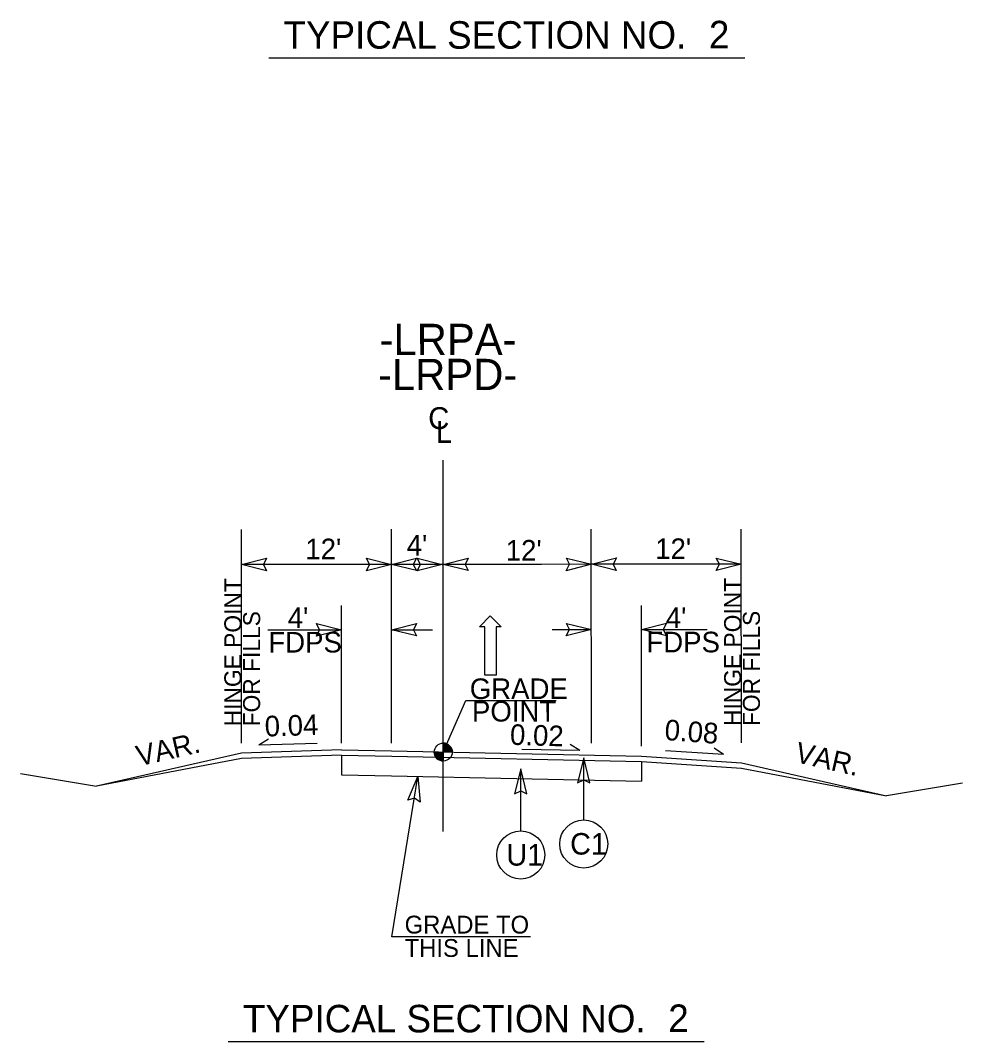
# Model space of a CAD drawing. Extents: x 2241081 to 2251104, y 658534 to 663427.
# Drawn here: x 2243910.9 to 2244287.9, y 660883.3 to 661291.9 of the extents above; entities that cross this region are included whole.
import ezdxf

# ---------------------------------------------------------------- set-up
doc = ezdxf.new("R2010")
doc.units = 0
for name, color, linetype in [('Old_Level_1', 7, 'Continuous'), ('Old_Level_11', 7, 'Continuous'), ('Old_Level_2', 7, 'Continuous'), ('Old_Level_3', 7, 'Continuous'), ('Prop Dimension Text', 7, 'Continuous'), ('Prop Lane Arrow CELL', 7, 'Continuous'), ('Prop PHM Text', 7, 'Continuous'), ('Typical Arrow Superelevation CELL', 7, 'Continuous'), ('Typical Berm Information CELL', 7, 'Continuous'), ('Typical Grade Point Symbol CELL', 7, 'Continuous'), ('Typical ID Circle CELL', 7, 'Continuous'), ('Typical Terminator CELL', 7, 'Continuous'), ('Typical Text Centerline CELL', 7, 'Continuous'), ('Typical Text Grade Point CELL', 7, 'Continuous'), ('Typical Text ID Circle CELL', 7, 'Continuous'), ('Typical Text Label CELL', 7, 'Continuous')]:
    doc.layers.add(name, color=color, linetype=linetype)

# ---------------------------------------------------------------- blocks, each defined once
blk = doc.blocks.new('TERMINATOR')
at = {"layer": 'Typical Terminator CELL'}
blk.add_lwpolyline([(-0.469, 0.081), (0, 0), (-0.471, -0.083), (-0.411, 0)], close=True, dxfattribs=at)

msp = doc.modelspace()

# ---------------------------------------------------------------- linework, layer by layer
at = {"layer": 'Old_Level_1'}
for p, q in [((2243999.39, 660998.69), (2243941.38, 660985.41)), ((2244199.38, 660994.85), (2244257.39, 660981.57))]:
    msp.add_line(p, q, dxfattribs=at)
at = {"layer": 'Old_Level_11'}
msp.add_line((2244059.46, 660925.15), (2244069.94, 660989.33), dxfattribs=at)
at = {"layer": 'Old_Level_2'}
for p, q in [((2244039.39, 660999.99), (2243999.39, 660998.69)), ((2244039.39, 660997.88), (2243999.39, 660996.58)), ((2244039.39, 660999.99), (2244059.39, 660999.56)), ((2244039.39, 660997.88), (2244039.39, 660989.99)), ((2244039.39, 660997.88), (2244059.49, 660997.45)), ((2244059.39, 660999.56), (2244159.39, 660997.42)), ((2244059.49, 660997.45), (2244159.39, 660995.31)), ((2244159.39, 660997.42), (2244199.38, 660994.85)), ((2243999.39, 660996.58), (2243941.38, 660985.41)), ((2244159.39, 660995.31), (2244159.39, 660987.42)), ((2244159.39, 660995.31), (2244199.38, 660992.73)), ((2244199.38, 660992.73), (2244257.39, 660981.57)), ((2243910.88, 660990.5), (2243941.38, 660985.41)), ((2244039.39, 660989.99), (2244059.38, 660989.56)), ((2244059.38, 660989.56), (2244159.39, 660987.42)), ((2244287.89, 660986.65), (2244257.39, 660981.57))]:
    msp.add_line(p, q, dxfattribs=at)
at = {"layer": 'Prop Dimension Text'}
for p, q in [((2243999.38, 661002.64), (2243999.33, 661088.23)), ((2244059.38, 661002.68), (2244059.33, 661088.27)), ((2244139.38, 661002.73), (2244139.33, 661088.32)), ((2244199.38, 661002.76), (2244199.33, 661088.35)), ((2244199.34, 661074.28), (2244139.34, 661074.25)), ((2244059.34, 661074.2), (2243999.34, 661074.16)), ((2244080.03, 661074.21), (2244059.34, 661074.2)), ((2244119.34, 661074.24), (2244080.03, 661074.21)), ((2244139.34, 661074.25), (2244119.34, 661074.24)), ((2244039.38, 661002.67), (2244039.35, 661057.75)), ((2244159.39, 661001.43), (2244159.35, 661057.82)), ((2244009.91, 661048.04), (2244039.36, 661048.06)), ((2244059.36, 661048.07), (2244075.73, 661048.08)), ((2244123.62, 661048.11), (2244139.36, 661048.12)), ((2244159.36, 661048.13), (2244185.69, 661048.15)), ((2244114.95, 660925.18), (2244059.46, 660925.15))]:
    msp.add_line(p, q, dxfattribs=at)
at = {"layer": 'Prop Lane Arrow CELL'}
for p, q in [((2244094.62, 661049.23), (2244098.89, 661053.57)), ((2244098.89, 661053.57), (2244103.31, 661049.23)), ((2244096.69, 661049.23), (2244094.62, 661049.23)), ((2244096.7, 661029.93), (2244096.69, 661049.23)), ((2244103.31, 661049.23), (2244101.24, 661049.23)), ((2244101.24, 661049.23), (2244101.25, 661029.94)), ((2244101.25, 661029.94), (2244096.7, 661029.93))]:
    msp.add_line(p, q, dxfattribs=at)
at = {"layer": 'Typical Arrow Superelevation CELL'}
for p, q in [((2244006.29, 661002.03), (2244010.18, 661004.43)), ((2244006.29, 661002.03), (2244029.59, 661002.73)), ((2244134.79, 660999.72), (2244130.87, 661002.08)), ((2244192.25, 660998.21), (2244188.44, 661000.74)), ((2244134.79, 660999.72), (2244111.49, 661000.18)), ((2244192.25, 660998.21), (2244168.99, 660999.67))]:
    msp.add_line(p, q, dxfattribs=at)
at = {"layer": 'Typical Grade Point Symbol CELL'}
for p, q in [((2244080.08, 661002.7), (2244080.07, 660999.12)), ((2244080.07, 660999.12), (2244080.08, 661002.7)), ((2244076.49, 660999.12), (2244080.07, 660999.12)), ((2244080.07, 660999.12), (2244080.07, 660995.54)), ((2244083.65, 660999.12), (2244080.07, 660999.12))]:
    msp.add_line(p, q, dxfattribs=at)
for points in [[(2244080.13, 660999.12), (2244080.13, 661002.7), (2244080.13, 661002.7)], [(2244080.2, 660999.12), (2244080.2, 661002.7)], [(2244080.27, 660999.12), (2244080.27, 661002.69)], [(2244080.34, 660999.12), (2244080.34, 661002.69)], [(2244080.42, 660999.12), (2244080.42, 661002.68)], [(2244080.49, 660999.12), (2244080.49, 661002.67)], [(2244080.56, 660999.12), (2244080.56, 661002.67)], [(2244080.63, 660999.12), (2244080.63, 661002.65)], [(2244080.7, 660999.12), (2244080.7, 661002.64)], [(2244080.77, 660999.12), (2244080.77, 661002.63)], [(2244080.84, 660999.12), (2244080.84, 661002.61)], [(2244080.92, 660999.12), (2244080.92, 661002.59)], [(2244080.99, 660999.12), (2244080.99, 661002.58)], [(2244081.06, 660999.12), (2244081.06, 661002.55)], [(2244081.13, 660999.12), (2244081.13, 661002.54)], [(2244081.2, 660999.12), (2244081.2, 661002.51)], [(2244081.27, 660999.12), (2244081.27, 661002.49)], [(2244081.35, 660999.12), (2244081.35, 661002.47)], [(2244081.42, 660999.12), (2244081.42, 661002.43)], [(2244081.49, 660999.12), (2244081.49, 661002.4)], [(2244081.56, 660999.12), (2244081.56, 661002.37)], [(2244081.63, 660999.12), (2244081.63, 661002.34)], [(2244081.7, 660999.12), (2244081.7, 661002.31)], [(2244081.78, 660999.12), (2244081.78, 661002.27)], [(2244081.85, 660999.12), (2244081.85, 661002.23)], [(2244081.92, 660999.12), (2244081.92, 661002.19)], [(2244081.99, 660999.12), (2244081.99, 661002.14)], [(2244082.06, 660999.12), (2244082.06, 661002.09)], [(2244082.13, 660999.12), (2244082.13, 661002.04)], [(2244082.21, 660999.12), (2244082.21, 661002)], [(2244082.28, 660999.12), (2244082.28, 661001.94)], [(2244082.35, 660999.12), (2244082.35, 661001.89)], [(2244082.42, 660999.12), (2244082.42, 661001.82)], [(2244082.49, 660999.12), (2244082.49, 661001.76)], [(2244082.56, 660999.12), (2244082.56, 661001.69)], [(2244082.64, 660999.12), (2244082.64, 661001.62)], [(2244082.71, 660999.12), (2244082.71, 661001.54)], [(2244082.78, 660999.12), (2244082.78, 661001.46)], [(2244082.85, 660999.12), (2244082.85, 661001.38)], [(2244082.92, 660999.12), (2244082.92, 661001.29)], [(2244082.99, 660999.12), (2244082.99, 661001.19)], [(2244083.06, 660999.12), (2244083.06, 661001.09)], [(2244083.14, 660999.12), (2244083.14, 661000.98)], [(2244083.21, 660999.12), (2244083.21, 661000.85)], [(2244076.53, 660998.61), (2244076.53, 660999.12)], [(2244076.6, 660998.24), (2244076.6, 660999.12)], [(2244076.68, 660997.99), (2244076.68, 660999.12)], [(2244076.75, 660997.8), (2244076.75, 660999.12)], [(2244076.82, 660997.63), (2244076.82, 660999.12)], [(2244076.89, 660997.48), (2244076.89, 660999.12)], [(2244076.96, 660997.35), (2244076.96, 660999.12)], [(2244077.03, 660997.23), (2244077.03, 660999.12)], [(2244077.11, 660997.12), (2244077.11, 660999.12)], [(2244077.18, 660997.02), (2244077.18, 660999.12)], [(2244077.25, 660996.92), (2244077.25, 660999.12)], [(2244077.32, 660996.83), (2244077.32, 660999.12)], [(2244077.39, 660996.75), (2244077.39, 660999.12)], [(2244077.46, 660996.67), (2244077.46, 660999.12)], [(2244077.54, 660996.59), (2244077.54, 660999.12)], [(2244077.61, 660996.52), (2244077.61, 660999.12)], [(2244077.68, 660996.46), (2244077.68, 660999.12)], [(2244077.75, 660996.39), (2244077.75, 660999.12)], [(2244077.82, 660996.33), (2244077.82, 660999.12)], [(2244077.89, 660996.28), (2244077.89, 660999.12)], [(2244077.96, 660996.23), (2244077.96, 660999.12)], [(2244078.04, 660996.17), (2244078.04, 660999.12)], [(2244078.11, 660996.12), (2244078.11, 660999.12)], [(2244078.18, 660996.08), (2244078.18, 660999.12)], [(2244078.25, 660996.04), (2244078.25, 660999.12)], [(2244078.32, 660996), (2244078.32, 660999.12)], [(2244078.39, 660995.96), (2244078.39, 660999.12)], [(2244078.47, 660995.92), (2244078.47, 660999.12)], [(2244078.54, 660995.89), (2244078.54, 660999.12)], [(2244078.61, 660995.85), (2244078.61, 660999.12)], [(2244078.68, 660995.82), (2244078.68, 660999.12)], [(2244078.75, 660995.79), (2244078.75, 660999.12)], [(2244078.82, 660995.76), (2244078.82, 660999.12)], [(2244078.9, 660995.73), (2244078.9, 660999.12)], [(2244078.97, 660995.71), (2244078.97, 660999.12)], [(2244079.04, 660995.69), (2244079.04, 660999.12)], [(2244079.11, 660995.67), (2244079.11, 660999.12)], [(2244079.18, 660995.65), (2244079.18, 660999.12)], [(2244079.25, 660995.63), (2244079.25, 660999.12)], [(2244079.33, 660995.62), (2244079.33, 660999.12)], [(2244079.4, 660995.6), (2244079.4, 660999.12)], [(2244079.47, 660995.58), (2244079.47, 660999.12)], [(2244079.54, 660995.58), (2244079.54, 660999.12)], [(2244079.61, 660995.57), (2244079.61, 660999.12)], [(2244079.68, 660995.56), (2244079.68, 660999.12)], [(2244079.76, 660995.55), (2244079.76, 660999.12)], [(2244079.83, 660995.54), (2244079.83, 660999.12)], [(2244079.9, 660995.54), (2244079.9, 660999.12)], [(2244079.97, 660995.54), (2244079.97, 660999.12)], [(2244080.04, 660995.54), (2244080.04, 660995.54), (2244080.04, 660999.12)], [(2244083.28, 660999.12), (2244083.28, 661000.72)], [(2244083.35, 660999.12), (2244083.35, 661000.56)], [(2244083.42, 660999.12), (2244083.42, 661000.4)], [(2244083.49, 660999.12), (2244083.49, 661000.18)], [(2244083.57, 660999.12), (2244083.57, 660999.93)], [(2244083.64, 660999.12), (2244083.64, 660999.51)]]:
    msp.add_lwpolyline(points, dxfattribs=at)
msp.add_circle((2244080.08, 660999.12), 3.58, dxfattribs=at)
for start, end in [(359.9905, 89.9905), (179.9905, 269.9905)]:
    msp.add_arc((2244080.08, 660999.12), 3.58, start, end, dxfattribs=at)
at = {"layer": 'Typical ID Circle CELL'}
for p, q in [((2244136.31, 660971.95), (2244136.31, 660996.8)), ((2244111.1, 660967.54), (2244111.1, 660992.4))]:
    msp.add_line(p, q, dxfattribs=at)
for centre in [(2244136.31, 660962.33), (2244111.1, 660957.93)]:
    msp.add_circle(centre, 9.62, dxfattribs=at)
at = {"layer": 'Typical Text Centerline CELL'}
msp.add_line((2244080.09, 660967.33), (2244080, 661115.88), dxfattribs=at)
at = {"layer": 'Typical Text Grade Point CELL'}
for p, q in [((2244080.07, 660999.12), (2244089.08, 661019.7)), ((2244089.08, 661019.7), (2244125.21, 661019.72))]:
    msp.add_line(p, q, dxfattribs=at)
at = {"layer": 'Typical Text Label CELL'}
for p, q in [((2244010.26, 661276.89), (2244200.74, 661276.89)), ((2243994, 660883.27), (2244184.49, 660883.27))]:
    msp.add_line(p, q, dxfattribs=at)

# ---------------------------------------------------------------- block references
at = {"layer": 'Typical Terminator CELL'}
for p, xscale, yscale, rotation in [((2243999.34, 661074.16), 21.314641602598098, 30.593161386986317, -179.96511250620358), ((2244059.34, 661074.2), 21.314641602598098, 30.593161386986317, 0.03488749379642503), ((2244059.34, 661074.2), 21.314641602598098, 30.593161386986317, -179.96511250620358), ((2244079.68, 661074.23), 21.314641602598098, 30.593161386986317, 0.03488749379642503), ((2244080.03, 661074.21), 21.314641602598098, 30.593161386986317, -179.96511250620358), ((2244139.34, 661074.25), 21.314641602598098, 30.593161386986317, 0.03488749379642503), ((2244139.34, 661074.25), 21.314641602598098, 30.593161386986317, -179.96511250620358), ((2244199.34, 661074.28), 21.314641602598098, 30.593161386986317, 0.03488749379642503), ((2244039.36, 661048.06), 21.314641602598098, 30.593161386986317, 0.03488749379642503), ((2244059.36, 661048.07), 21.314641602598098, 30.593161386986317, -179.96511250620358), ((2244139.36, 661048.12), 21.314641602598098, 30.593161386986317, 0.03488749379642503), ((2244159.36, 661048.13), 21.314641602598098, 30.593161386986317, -179.96511250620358), ((2244136.31, 660996.8), 21.3146416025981, -30.593161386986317, 89.9999349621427), ((2244069.94, 660989.33), 21.314641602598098, 30.593161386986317, 80.72833125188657), ((2244111.1, 660992.4), 21.3146416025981, -30.593161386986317, 89.9999349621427)]:
    msp.add_blockref('TERMINATOR', p, dxfattribs=dict(at, xscale=xscale, yscale=yscale, rotation=rotation))

# ---------------------------------------------------------------- texts
at = {"layer": 'Old_Level_3'}
for s, p in [('GRADE TO', (2244064.63, 660926.5)), ('THIS LINE', (2244064.63, 660917.15))]:
    msp.add_text(s, height=7.131, rotation=359.9999, dxfattribs=at).set_placement(p)
at = {"layer": 'Prop Dimension Text'}
for s, height, rotation, p in [('-LRPA-', 12.5, 0.0349, (2244054.61, 661157.99)), ('-LRPD-', 12.5, 0.0349, (2244053.98, 661143.96)), ("12'", 8.25, 0.0349, (2244024.9, 661076.27)), ("4'", 8.25, 0.0349, (2244065.46, 661077.75)), ("12'", 8.25, 0.0349, (2244105.1, 661075.74)), ("12'", 8.25, 0.0349, (2244164.9, 661076.35)), ("4'", 8.25, 0.0349, (2244017.84, 661048.72)), ("4'", 8.25, 0.0349, (2244169.13, 661048.78)), ('FDPS', 8.25, 0.0349, (2244010.09, 661038.94)), ('FDPS', 8.25, 0.0349, (2244161.38, 661039)), ('VAR.', 8.25, 12.8903, (2243958.29, 660993.38)), ('VAR.', 8.25, 347.1096, (2244220.44, 660995.21))]:
    msp.add_text(s, height=height, rotation=rotation, dxfattribs=at).set_placement(p)
at = {"layer": 'Prop PHM Text'}
for s, height, p in [('HINGE POINT', 6.8193, (2243999.29, 661009.41)), ('HINGE POINT', 6.8193, (2244199.29, 661009.54)), ('FOR FILLS', 6.819, (2244006.8, 661009.41)), ('FOR FILLS', 6.819, (2244206.8, 661009.54))]:
    msp.add_text(s, height=height, rotation=89.9999, dxfattribs=at).set_placement(p)
at = {"layer": 'Typical Berm Information CELL'}
for s, rotation, p in [('0.04', 1.7135, (2244008.75, 661005.32)), ('0.02 ', 358.1916, (2244106.69, 661002.05)), ('0.08', 355.7379, (2244168.44, 661003.98))]:
    msp.add_text(s, height=8.25, rotation=rotation, dxfattribs=at).set_placement(p)
at = {"layer": 'Typical Text Centerline CELL'}
for s, rotation, p in [('C', 0.0349, (2244074.06, 661128.36)), ('L', 359.9818, (2244077.09, 661122.86))]:
    msp.add_text(s, height=8.76, rotation=rotation, dxfattribs=at).set_placement(p)
at = {"layer": 'Typical Text Grade Point CELL'}
for s, p in [('GRADE', (2244090.7, 661020.32)), ('POINT', (2244091.57, 661011.32))]:
    msp.add_text(s, height=8.25, rotation=0.0349, dxfattribs=at).set_placement(p)
at = {"layer": 'Typical Text ID Circle CELL'}
for s, p in [('C1', (2244130.86, 660958.1)), ('U1', (2244105.33, 660953.69))]:
    msp.add_text(s, height=8.608, rotation=359.9999, dxfattribs=at).set_placement(p)
at = {"layer": 'Typical Text Label CELL'}
for s, height, p in [('TYPICAL SECTION NO.  ', 11.0106, (2244016.16, 661280.58)), ('2', 11.01, (2244186.39, 661280.72)), ('TYPICAL SECTION NO.  ', 11.0106, (2243999.91, 660886.95)), ('2', 11.01, (2244170.13, 660887.1))]:
    msp.add_text(s, height=height, dxfattribs=at).set_placement(p)

doc.saveas('drawing.dxf')
